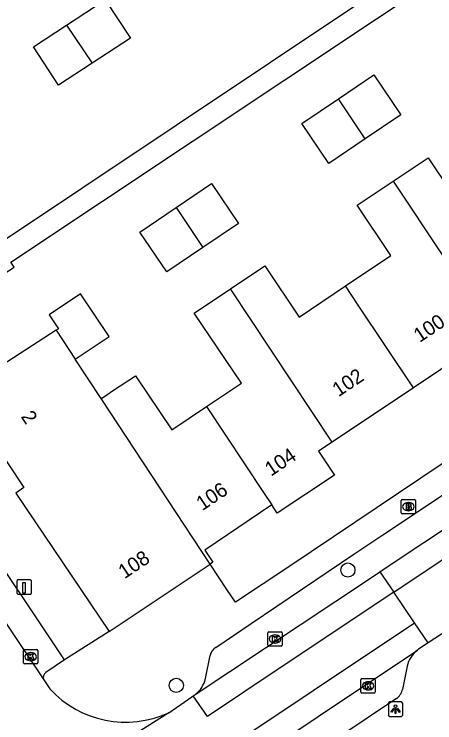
# Model space of a CAD drawing. Extents: x 158352 to 159489, y 383828 to 384597.
# Drawn here: x 158805.82 to 158834.96, y 384209.34 to 384258.46 of the extents above; entities that cross this region are included whole.
import ezdxf

# ---------------------------------------------------------------- set-up
doc = ezdxf.new("R2010")
doc.units = 0
for name, color, linetype in [('IMGEO_Boom', 7, 'Continuous'), ('IMGEO_Brandkraan', 7, 'Continuous'), ('IMGEO_Kolk', 7, 'Continuous'), ('IMGEO_Laadpaal', 7, 'Continuous'), ('IMGEO_Lichtpunt', 7, 'Continuous'), ('IMGEO_Pand', 7, 'Continuous'), ('IMGEO_Pand_nummerreeks', 7, 'Continuous'), ('IMGEO_Rijbaan_lokaal_gesloten', 7, 'Continuous'), ('IMGEO_Rijbaan_lokaal_open', 7, 'Continuous'), ('IMGEO_Voetpad_open', 7, 'Continuous')]:
    doc.layers.add(name, color=color, linetype=linetype)

msp = doc.modelspace()

# ---------------------------------------------------------------- linework, layer by layer
at = {"layer": 'IMGEO_Boom'}
for centre in [(158828.94, 384219.928), (158817.052, 384211.934)]:
    msp.add_circle(centre, 0.489, dxfattribs=at)
at = {"layer": 'IMGEO_Brandkraan'}
for p, q in [((158832.627, 384223.896), (158832.627, 384224.748)), ((158832.702, 384224.822), (158833.554, 384224.822)), ((158833.628, 384224.748), (158833.628, 384223.896)), ((158833.115, 384224.602), (158833.14, 384224.602)), ((158833.554, 384223.822), (158832.702, 384223.822)), ((158833.138, 384224.042), (158833.113, 384224.042))]:
    msp.add_line(p, q, dxfattribs=at)
for points in [[(158832.627, 384223.896), (158832.627, 384224.748)], [(158832.702, 384224.822), (158833.554, 384224.822)], [(158833.628, 384224.748), (158833.628, 384223.896)], [(158832.975, 384224.522), (158832.975, 384224.122), (158833.188, 384224.122)], [(158833.206, 384224.522), (158832.975, 384224.522)], [(158833.154, 384224.441), (158833.1, 384224.441), (158833.1, 384224.365)], [(158833.1, 384224.365), (158833.153, 384224.365)], [(158833.162, 384224.289), (158833.1, 384224.289), (158833.1, 384224.208)], [(158833.1, 384224.208), (158833.162, 384224.208)], [(158833.554, 384223.822), (158832.702, 384223.822)]]:
    msp.add_lwpolyline(points, dxfattribs=at)
for centre, radius, start, end in [((158832.704, 384224.746), 0.0765, 91.552, 178.448), ((158832.704, 384224.746), 0.0765, 91.552, 178.448), ((158833.552, 384224.746), 0.0765, 1.552, 88.448), ((158833.552, 384224.746), 0.0765, 1.552, 88.448), ((158833.155, 384224.403), 0.0379, 267.8285, 90.9355), ((158833.163, 384224.248), 0.0404, 269.8759, 90.5077), ((158833.194, 384224.373), 0.251, 268.6676, 293.5347), ((158833.21, 384224.377), 0.145, 59.4692, 91.5367), ((158833.235, 384224.424), 0.0922, 285.5137, 58.1501), ((158833.24, 384224.232), 0.105, 301.3115, 78.989), ((158832.704, 384223.898), 0.0765, 181.552, 268.448), ((158832.704, 384223.898), 0.0765, 181.552, 268.448), ((158833.552, 384223.898), 0.0765, 271.552, 358.448), ((158833.552, 384223.898), 0.0765, 271.552, 358.448)]:
    msp.add_arc(centre, radius, start, end, dxfattribs=at)
for centre, major_axis, ratio, start_param, end_param in [((158833.114, 384224.322), (-0.387, 0.002), 0.722429, 4.712389, 7.853982), ((158833.139, 384224.322), (-0.39, 0.002), 0.717154, 1.570796, 4.712389)]:
    msp.add_ellipse(centre, major_axis=major_axis, ratio=ratio, start_param=start_param, end_param=end_param, dxfattribs=at)
at = {"layer": 'IMGEO_Kolk'}
for p, q in [((158823.389, 384214.722), (158823.389, 384215.574)), ((158823.464, 384215.648), (158824.316, 384215.648)), ((158823.877, 384215.428), (158823.902, 384215.428)), ((158824.39, 384215.574), (158824.39, 384214.722)), ((158823.9, 384214.868), (158823.875, 384214.868)), ((158806.466, 384213.496), (158806.466, 384214.348)), ((158806.541, 384214.422), (158807.393, 384214.422)), ((158807.467, 384214.348), (158807.467, 384213.496)), ((158824.316, 384214.648), (158823.464, 384214.648)), ((158806.954, 384214.202), (158806.979, 384214.202)), ((158807.393, 384213.422), (158806.541, 384213.422)), ((158806.977, 384213.642), (158806.952, 384213.642)), ((158829.834, 384211.474), (158829.834, 384212.326)), ((158829.909, 384212.4), (158830.761, 384212.4)), ((158830.835, 384212.326), (158830.835, 384211.474)), ((158830.322, 384212.18), (158830.347, 384212.18)), ((158830.761, 384211.4), (158829.909, 384211.4)), ((158830.345, 384211.62), (158830.32, 384211.62))]:
    msp.add_line(p, q, dxfattribs=at)
for points in [[(158823.389, 384214.722), (158823.389, 384215.574)], [(158823.464, 384215.648), (158824.316, 384215.648)], [(158823.71, 384215.348), (158823.833, 384215.348), (158823.833, 384215.197), (158823.963, 384215.348), (158824.127, 384215.348), (158823.981, 384215.197), (158824.134, 384214.948), (158823.982, 384214.948), (158823.897, 384215.112), (158823.833, 384215.045), (158823.833, 384214.948), (158823.71, 384214.948), (158823.71, 384215.348)], [(158824.39, 384215.574), (158824.39, 384214.722)], [(158806.466, 384213.496), (158806.466, 384214.348)], [(158806.541, 384214.422), (158807.393, 384214.422)], [(158807.467, 384214.348), (158807.467, 384213.496)], [(158824.316, 384214.648), (158823.464, 384214.648)], [(158806.787, 384214.122), (158806.91, 384214.122), (158806.91, 384213.971), (158807.04, 384214.122), (158807.204, 384214.122), (158807.058, 384213.971), (158807.211, 384213.722), (158807.059, 384213.722), (158806.974, 384213.886), (158806.91, 384213.819), (158806.91, 384213.722), (158806.787, 384213.722), (158806.787, 384214.122)], [(158807.393, 384213.422), (158806.541, 384213.422)], [(158829.834, 384211.474), (158829.834, 384212.326)], [(158829.909, 384212.4), (158830.761, 384212.4)], [(158830.835, 384212.326), (158830.835, 384211.474)], [(158830.155, 384212.1), (158830.278, 384212.1), (158830.278, 384211.949), (158830.408, 384212.1), (158830.572, 384212.1), (158830.426, 384211.949), (158830.579, 384211.7), (158830.427, 384211.7), (158830.342, 384211.864), (158830.278, 384211.797), (158830.278, 384211.7), (158830.155, 384211.7), (158830.155, 384212.1)], [(158830.761, 384211.4), (158829.909, 384211.4)]]:
    msp.add_lwpolyline(points, dxfattribs=at)
for centre, start, end in [((158823.466, 384215.572), 91.552, 178.448), ((158823.466, 384215.572), 91.552, 178.448), ((158824.314, 384215.572), 1.552, 88.448), ((158824.314, 384215.572), 1.552, 88.448), ((158806.543, 384214.346), 91.552, 178.448), ((158806.543, 384214.346), 91.552, 178.448), ((158807.391, 384214.346), 1.552, 88.448), ((158807.391, 384214.346), 1.552, 88.448), ((158823.466, 384214.724), 181.552, 268.448), ((158823.466, 384214.724), 181.552, 268.448), ((158824.314, 384214.724), 271.552, 358.448), ((158824.314, 384214.724), 271.552, 358.448), ((158806.543, 384213.498), 181.552, 268.448), ((158806.543, 384213.498), 181.552, 268.448), ((158807.391, 384213.498), 271.552, 358.448), ((158807.391, 384213.498), 271.552, 358.448), ((158829.911, 384212.324), 91.552, 178.448), ((158829.911, 384212.324), 91.552, 178.448), ((158830.759, 384212.324), 1.552, 88.448), ((158830.759, 384212.324), 1.552, 88.448), ((158829.911, 384211.476), 181.552, 268.448), ((158829.911, 384211.476), 181.552, 268.448), ((158830.759, 384211.476), 271.552, 358.448), ((158830.759, 384211.476), 271.552, 358.448)]:
    msp.add_arc(centre, 0.0765, start, end, dxfattribs=at)
for centre, major_axis, ratio, start_param, end_param in [((158823.876, 384215.148), (-0.387, 0.002), 0.722429, 4.712389, 7.853982), ((158823.901, 384215.148), (-0.39, 0.002), 0.717154, 1.570796, 4.712389), ((158806.953, 384213.922), (-0.387, 0.002), 0.722429, 4.712389, 7.853982), ((158806.978, 384213.922), (-0.39, 0.002), 0.717154, 1.570796, 4.712389), ((158830.321, 384211.9), (-0.387, 0.002), 0.722429, 4.712389, 7.853982), ((158830.346, 384211.9), (-0.39, 0.002), 0.717154, 1.570796, 4.712389)]:
    msp.add_ellipse(centre, major_axis=major_axis, ratio=ratio, start_param=start_param, end_param=end_param, dxfattribs=at)
at = {"layer": 'IMGEO_Laadpaal'}
for p, q in [((158806.93, 384219.252), (158806.089, 384219.252)), ((158806.93, 384219.252), (158806.089, 384219.252)), ((158806.014, 384219.168), (158806.014, 384218.327)), ((158806.014, 384219.168), (158806.014, 384218.327)), ((158807.014, 384218.336), (158807.014, 384219.177)), ((158807.014, 384218.336), (158807.014, 384219.177)), ((158806.098, 384218.252), (158806.939, 384218.252)), ((158806.098, 384218.252), (158806.939, 384218.252))]:
    msp.add_line(p, q, dxfattribs=at)
msp.add_lwpolyline([(158806.429, 384219.065), (158806.589, 384219.065), (158806.589, 384218.332), (158806.429, 384218.332), (158806.429, 384219.065)], dxfattribs=at)
for centre, start, end in [((158806.092, 384219.174), 92.4484, 184.2845), ((158806.092, 384219.174), 92.4484, 184.2845), ((158806.936, 384219.174), 2.4484, 94.2845), ((158806.936, 384219.174), 2.4484, 94.2845), ((158806.092, 384218.33), 182.4484, 274.2845), ((158806.092, 384218.33), 182.4484, 274.2845), ((158806.936, 384218.33), 272.4484, 4.2845), ((158806.936, 384218.33), 272.4484, 4.2845)]:
    msp.add_arc(centre, 0.0779, start, end, dxfattribs=at)
at = {"layer": 'IMGEO_Lichtpunt'}
for p, q in [((158831.74, 384210.686), (158831.74, 384209.879)), ((158831.74, 384210.686), (158831.74, 384209.879)), ((158832.642, 384210.781), (158831.834, 384210.781)), ((158832.642, 384210.781), (158831.834, 384210.781)), ((158832.736, 384209.879), (158832.736, 384210.686)), ((158832.736, 384209.879), (158832.736, 384210.686)), ((158831.834, 384209.785), (158832.642, 384209.785)), ((158831.834, 384209.785), (158832.642, 384209.785))]:
    msp.add_line(p, q, dxfattribs=at)
for points in [[(158832.114, 384210.35), (158832.153, 384210.322), (158831.965, 384210.06), (158831.927, 384210.087), (158832.114, 384210.35)], [(158832.216, 384210.302), (158832.263, 384210.302), (158832.263, 384209.98), (158832.216, 384209.98), (158832.216, 384210.302)], [(158832.326, 384210.322), (158832.364, 384210.349), (158832.551, 384210.087), (158832.512, 384210.059), (158832.326, 384210.322)]]:
    msp.add_lwpolyline(points, dxfattribs=at)
msp.add_circle((158832.239, 384210.484), 0.0994, dxfattribs=at)
for centre, start, end in [((158831.834, 384210.686), 90, 180), ((158831.834, 384210.686), 90, 180), ((158832.642, 384210.686), 0, 90), ((158832.642, 384210.686), 0, 90), ((158831.834, 384209.879), 180, 270), ((158831.834, 384209.879), 180, 270), ((158832.642, 384209.879), 270, 0), ((158832.642, 384209.879), 270, 360)]:
    msp.add_arc(centre, 0.0946, start, end, dxfattribs=at)
at = {"layer": 'IMGEO_Pand'}
for points in [[(158809.446, 384257.704), (158812.131, 384259.469), (158813.882, 384256.805), (158811.226, 384255.059)], [(158811.226, 384255.059), (158808.9, 384253.53), (158807.149, 384256.194), (158809.446, 384257.704)], [(158809.446, 384257.704), (158811.226, 384255.059)], [(158828.281, 384252.594), (158830.733, 384254.248), (158832.6, 384251.479), (158830.128, 384249.812)], [(158830.128, 384249.812), (158827.619, 384248.12), (158825.752, 384250.888), (158828.281, 384252.594)], [(158830.128, 384249.812), (158828.281, 384252.594)], [(158832.074, 384246.881), (158834.499, 384248.506), (158837.737, 384243.675), (158840.338, 384245.418)], [(158817.047, 384245.065), (158819.5, 384246.719), (158821.367, 384243.95), (158818.894, 384242.283)], [(158828.782, 384239.625), (158831.923, 384241.729), (158829.587, 384245.214), (158832.074, 384246.881)], [(158832.074, 384246.881), (158839.085, 384236.32)], [(158818.894, 384242.283), (158816.386, 384240.591), (158814.519, 384243.359), (158817.047, 384245.065)], [(158817.047, 384245.065), (158818.894, 384242.283)], [(158820.797, 384239.417), (158823.181, 384241.015), (158825.56, 384237.466), (158828.782, 384239.625)], [(158819.145, 384231.264), (158821.558, 384232.881), (158818.299, 384237.743), (158820.797, 384239.417)], [(158827.853, 384228.79), (158820.797, 384239.417)], [(158833.473, 384232.558), (158829.661, 384238.301), (158828.782, 384239.625)], [(158810.043, 384234.549), (158810.257, 384234.693), (158810.602, 384234.924), (158812.397, 384236.128), (158810.421, 384239.077), (158808.254, 384237.625), (158808.886, 384236.65), (158808.728, 384236.548)], [(158808.728, 384236.548), (158802.014, 384232.216)], [(158808.728, 384236.548), (158810.043, 384234.549)], [(158839.085, 384236.32), (158833.473, 384232.558)], [(158811.844, 384231.81), (158810.043, 384234.549)], [(158811.844, 384231.81), (158812.082, 384231.97), (158812.635, 384232.341), (158814.216, 384233.401), (158816.732, 384229.647), (158819.145, 384231.264)], [(158833.473, 384232.558), (158827.853, 384228.79)], [(158802.014, 384232.216), (158802.088, 384232.09), (158802.178, 384232.143), (158806.493, 384225.639), (158805.937, 384225.266), (158812.392, 384215.663)], [(158819.391, 384220.337), (158811.844, 384231.81)], [(158819.145, 384231.264), (158823.095, 384225.314), (158823.675, 384224.44)], [(158827.853, 384228.79), (158826.913, 384228.16), (158828.008, 384226.51), (158824.046, 384223.882), (158823.675, 384224.44)], [(158823.675, 384224.44), (158819.034, 384221.302), (158819.59, 384220.47), (158819.391, 384220.337)], [(158812.392, 384215.663), (158819.391, 384220.337)]]:
    msp.add_lwpolyline(points, dxfattribs=at)
at = {"layer": 'IMGEO_Rijbaan_lokaal_gesloten'}
for points in [[(158831.156, 384219.806), (158832.496, 384220.707), (158842.526, 384227.357), (158843.894, 384228.271)], [(158832.123, 384218.384), (158844.821, 384226.897)], [(158818.36, 384211.295), (158830.503, 384219.367), (158831.156, 384219.806)], [(158831.156, 384219.806), (158832.123, 384218.384)], [(158832.123, 384218.384), (158824.254, 384213.149), (158819.204, 384209.77), (158818.226, 384211.198)], [(158792.434, 384186.755), (158791.418, 384188.112), (158833.556, 384216.278)], [(158834.508, 384214.879), (158833.831, 384214.44), (158833.75, 384214.368)], [(158792.599, 384186.878), (158833.75, 384214.368)], [(158818.226, 384211.198), (158818.36, 384211.295)]]:
    msp.add_lwpolyline(points, dxfattribs=at)
at = {"layer": 'IMGEO_Rijbaan_lokaal_open'}
for points in [[(158794.663, 384232.054), (158807.872, 384212.309)], [(158833.556, 384216.278), (158832.123, 384218.384)], [(158834.508, 384214.879), (158833.556, 384216.278)], [(158835.895, 384215.779), (158834.508, 384214.879)], [(158807.872, 384212.309), (158808.29, 384211.696)], [(158816.531, 384210.036), (158818.138, 384211.137), (158818.226, 384211.198)], [(158816.531, 384210.036), (158803.043, 384201.515)]]:
    msp.add_lwpolyline(points, dxfattribs=at)
msp.add_arc((158813.544, 384216.495), 7.116, 222.405, 294.8174, dxfattribs=at)
at = {"layer": 'IMGEO_Voetpad_open'}
for points in [[(158797.703, 384237.844), (158887.956, 384298.193), (158887.726, 384305.076)], [(158798.702, 384236.335), (158805.826, 384240.925), (158805.594, 384241.274), (158881.501, 384291.844), (158886.407, 384295.232), (158886.61, 384294.938), (158886.683, 384294.994)], [(158904.752, 384277.514), (158906.1, 384275.563), (158906.452, 384275.023), (158824.924, 384220.195), (158821.151, 384217.705), (158820.552, 384218.57), (158819.391, 384220.337)], [(158819.794, 384214.568), (158822.229, 384216.216), (158829.341, 384221.029), (158831.356, 384222.372), (158841.384, 384229.054), (158843.37, 384230.376), (158909.63, 384274.668)], [(158809.312, 384213.713), (158796.503, 384232.882)], [(158812.392, 384215.663), (158809.312, 384213.713)], [(158819.081, 384212.411), (158819.391, 384214.001)], [(158809.312, 384213.713), (158808.025, 384212.833)], [(158833.039, 384213.257), (158832.717, 384211.648)], [(158832.309, 384211.014), (158828.308, 384208.343)]]:
    msp.add_lwpolyline(points, dxfattribs=at)
for centre, radius, start, end in [((158820.192, 384213.859), 0.813, 119.2796, 169.9132), ((158834.927, 384212.831), 1.936, 127.4628, 167.3017), ((158808.273, 384212.476), 0.435, 124.8324, 202.6136), ((158817.086, 384212.909), 2.057, 308.2887, 345.9818), ((158831.673, 384211.871), 1.067, 306.5522, 347.9226)]:
    msp.add_arc(centre, radius, start, end, dxfattribs=at)

# ---------------------------------------------------------------- texts
at = {"layer": 'IMGEO_Pand_nummerreeks'}
for s, rotation, p in [('100', 33.8332, (158833.91, 384235.666)), ('102', 33.8332, (158828.288, 384231.899)), ('2', 303.5465, (158806.25, 384230.566)), ('104', 33.8217, (158823.609, 384226.394)), ('106', 33.8389, (158818.858, 384224.01)), ('108', 33.8332, (158813.461, 384219.283))]:
    msp.add_text(s, height=1, rotation=rotation, dxfattribs=at).set_placement(p)

doc.saveas('drawing.dxf')
